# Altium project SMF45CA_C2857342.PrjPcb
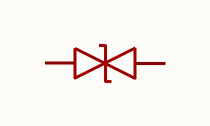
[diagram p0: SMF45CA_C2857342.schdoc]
1 sheet, 1 parts. Net scope: global (net labels, ports and power ports of the same name join across sheets).

## Sheet SMF45CA_C2857342.schdoc
size 127 x 101 mm

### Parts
D?  smf45ca_c2857342  [SOD-123FL_L2.8-W1.8-LS3.7-BI]  (value not drawn)

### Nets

Not connected (* = marked no-connect by the designer): D? 1(K) 2(A)

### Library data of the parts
D? = smf45ca_c2857342: 极性:双向;反向截止电压(Vrwm):45V;钳位电压:72.7V;峰值脉冲电流(Ipp):2.8A;峰值脉冲功率(Ppp):200W@10/1000us;击穿电压(VBR):50V;; Manufacturer: JSMSEMI(杰盛微); AddInBom: yes; ModelId: d105299b3871451c86f679efef28ff8f; ModelTransform: 145.669,70.866,0,0,0,0,0,0,0; Polarity: 双向; Reverse Stand-Off Voltage (Vrwm): 45V; Clamping Voltage: 72.7V; Peak Pulse Current (Ipp): 2.8A; Voltage - Breakdown: 50V; Reverse Leakage Current (Ir): 1uA; Number of Channels: 单路; Type: TVS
